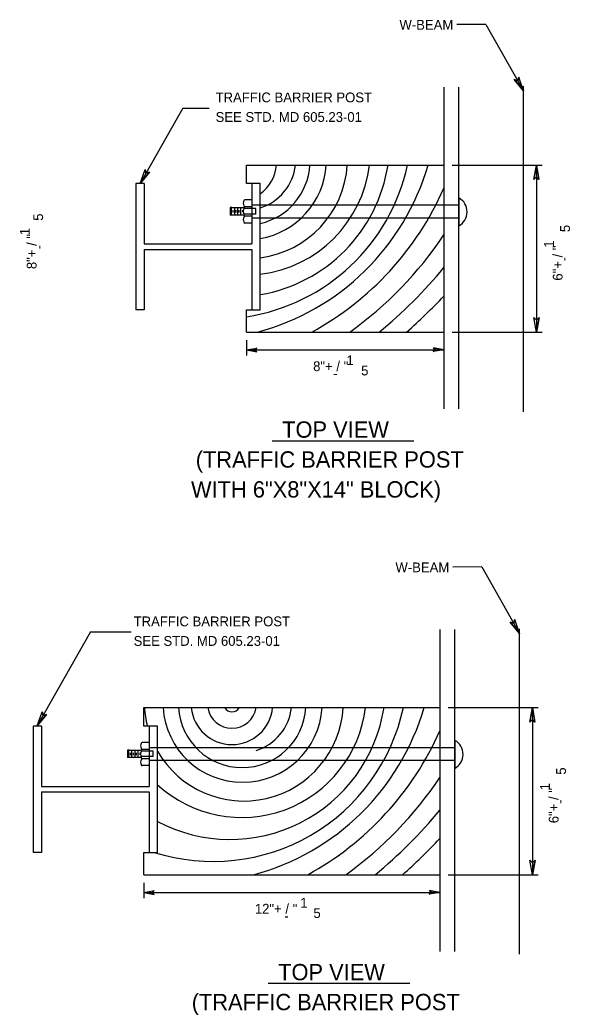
# Model space of a CAD drawing. Extents: x 12.3 to 19.6, y 6 to 16.3.
# Drawn here: x 16.17 to 19.54, y 10.17 to 16.27 of the extents above; entities that cross this region are included whole.
import ezdxf

# ---------------------------------------------------------------- set-up
doc = ezdxf.new("R2010")
doc.units = 0
for name, color, linetype in [('DETL-DIMS', 7, 'Continuous'), ('DETL-LINE', 7, 'Continuous'), ('DETL-NOTE', 7, 'Continuous'), ('DETL-PATT', 7, 'Continuous'), ('DETL-TITL', 7, 'Continuous')]:
    doc.layers.add(name, color=color, linetype=linetype)

msp = doc.modelspace()

# ---------------------------------------------------------------- linework, layer by layer
at = {"layer": 'DETL-DIMS'}
for p, q in [((19.0236, 16.2437), (18.8469, 16.2429)), ((19.0236, 16.2437), (19.2555, 15.8355)), ((19.2197, 15.8986), (19.2251, 15.9211)), ((19.2555, 15.8355), (19.2251, 15.9211)), ((19.2555, 15.8355), (19.1978, 15.9056)), ((19.1978, 15.9056), (19.2197, 15.8986)), ((17.1679, 15.7311), (16.9053, 15.2688)), ((17.1679, 15.7311), (17.3294, 15.7311)), ((18.8167, 15.3816), (19.3689, 15.3816)), ((19.3339, 15.3816), (19.3176, 15.2923)), ((19.3339, 15.3816), (19.3491, 15.2921)), ((19.3339, 15.3816), (19.3339, 14.3573)), ((16.9053, 15.2688), (16.9358, 15.3544)), ((16.9053, 15.2688), (16.963, 15.3389)), ((16.9412, 15.3319), (16.9358, 15.3544)), ((16.963, 15.3389), (16.9412, 15.3319)), ((19.3176, 15.2923), (19.3333, 15.3091)), ((19.3333, 15.3091), (19.3491, 15.2921)), ((19.3339, 14.3573), (19.3187, 14.4469)), ((19.3344, 14.4299), (19.3187, 14.4469)), ((19.3339, 14.3573), (19.3501, 14.4466)), ((19.3501, 14.4466), (19.3344, 14.4299)), ((18.8167, 14.3573), (19.3689, 14.3573)), ((17.5571, 14.3073), (17.5571, 14.2138)), ((17.5571, 14.2488), (17.6218, 14.2598)), ((17.5571, 14.2488), (17.6216, 14.237)), ((17.5571, 14.2488), (18.7667, 14.2488)), ((17.6095, 14.2485), (17.6218, 14.2598)), ((17.6216, 14.237), (17.6095, 14.2485)), ((18.7143, 14.2492), (18.7021, 14.2378)), ((18.7667, 14.2488), (18.7021, 14.2378)), ((18.7667, 14.2488), (18.7022, 14.2606)), ((18.7022, 14.2606), (18.7143, 14.2492)), ((18.999, 12.9184), (18.8223, 12.9176)), ((18.999, 12.9184), (19.2309, 12.5102)), ((19.2309, 12.5102), (19.1732, 12.5803)), ((19.1732, 12.5803), (19.1951, 12.5733)), ((19.1951, 12.5733), (19.2005, 12.5958)), ((19.2309, 12.5102), (19.2005, 12.5958)), ((16.6024, 12.5198), (16.2755, 11.9443)), ((16.6024, 12.5198), (16.8504, 12.5198)), ((16.2755, 11.9443), (16.306, 12.0299)), ((16.3114, 12.0074), (16.306, 12.0299)), ((18.7921, 12.0563), (19.3443, 12.0563)), ((19.3093, 12.0563), (19.293, 11.967)), ((19.3093, 12.0563), (19.3245, 11.9668)), ((19.3093, 12.0563), (19.3093, 11.032)), ((16.2755, 11.9443), (16.3332, 12.0144)), ((16.3332, 12.0144), (16.3114, 12.0074)), ((19.293, 11.967), (19.3087, 11.9838)), ((19.3087, 11.9838), (19.3245, 11.9668)), ((19.3093, 11.032), (19.2941, 11.1216)), ((19.3098, 11.1046), (19.2941, 11.1216)), ((19.3093, 11.032), (19.3255, 11.1213)), ((19.3255, 11.1213), (19.3098, 11.1046)), ((16.9278, 10.982), (16.9278, 10.8885)), ((18.7921, 11.032), (19.3443, 11.032)), ((16.9278, 10.9235), (16.9925, 10.9345)), ((16.9278, 10.9235), (16.9923, 10.9117)), ((16.9278, 10.9235), (18.7421, 10.9235)), ((16.9802, 10.9232), (16.9925, 10.9345)), ((16.9923, 10.9117), (16.9802, 10.9232)), ((18.6897, 10.9239), (18.6775, 10.9125)), ((18.7421, 10.9235), (18.6775, 10.9125)), ((18.7421, 10.9235), (18.6776, 10.9353)), ((18.6776, 10.9353), (18.6897, 10.9239))]:
    msp.add_line(p, q, dxfattribs=at)
for points in [[(19.1978, 15.9056), (19.2555, 15.8355), (19.2251, 15.9211), (19.2197, 15.8986)], [(19.3176, 15.2923), (19.3339, 15.3816), (19.3491, 15.2921), (19.3333, 15.3091)], [(16.963, 15.3389), (16.9053, 15.2688), (16.9358, 15.3544), (16.9412, 15.3319)], [(19.3501, 14.4466), (19.3339, 14.3573), (19.3187, 14.4469), (19.3344, 14.4299)], [(17.6216, 14.237), (17.5571, 14.2488), (17.6218, 14.2598), (17.6095, 14.2485)], [(18.7022, 14.2606), (18.7667, 14.2488), (18.7021, 14.2378), (18.7143, 14.2492)], [(19.1732, 12.5803), (19.2309, 12.5102), (19.2005, 12.5958), (19.1951, 12.5733)], [(16.3332, 12.0144), (16.2755, 11.9443), (16.306, 12.0299), (16.3114, 12.0074)], [(19.293, 11.967), (19.3093, 12.0563), (19.3245, 11.9668), (19.3087, 11.9838)], [(19.3255, 11.1213), (19.3093, 11.032), (19.2941, 11.1216), (19.3098, 11.1046)], [(16.9923, 10.9117), (16.9278, 10.9235), (16.9925, 10.9345), (16.9802, 10.9232)], [(18.6776, 10.9353), (18.7421, 10.9235), (18.6775, 10.9125), (18.6897, 10.9239)]]:
    msp.add_lwpolyline(points, close=True, dxfattribs=at)
at = {"layer": 'DETL-LINE'}
for p, q in [((18.7667, 15.8595), (18.7667, 13.887)), ((18.858, 13.8866), (18.858, 15.8595)), ((19.2555, 13.8699), (19.2555, 15.8652)), ((17.5573, 15.2688), (17.5573, 15.3816)), ((17.5573, 15.3816), (18.7667, 15.3816)), ((16.8799, 15.2688), (16.8799, 14.4944)), ((16.9306, 15.2688), (16.8799, 15.2688)), ((16.9306, 15.2688), (16.9306, 14.8985)), ((17.6418, 15.2688), (17.5573, 15.2688)), ((17.591, 15.2688), (17.591, 14.8985)), ((17.6418, 14.4944), (17.6418, 15.2688)), ((17.591, 15.1679), (17.5471, 15.1679)), ((17.591, 15.1371), (18.8633, 15.1371)), ((18.8584, 15.1808), (18.8577, 15.0083)), ((17.4683, 15.1206), (17.4584, 15.1206)), ((17.4584, 15.1206), (17.4584, 15.0748)), ((17.4832, 15.0749), (17.4584, 15.0749)), ((17.4644, 15.1206), (17.4644, 15.0749)), ((17.4644, 15.1206), (17.4832, 15.1206)), ((17.4832, 15.1206), (17.4832, 15.0749)), ((17.4832, 15.1206), (17.5417, 15.1206)), ((17.541, 15.0749), (17.4832, 15.0749)), ((17.5018, 15.1206), (17.5018, 15.0749)), ((17.5206, 15.1206), (17.5206, 15.0749)), ((17.6147, 15.0812), (17.5392, 15.0812)), ((17.6147, 15.1145), (17.5397, 15.1145)), ((17.591, 15.1258), (17.5471, 15.1258)), ((17.591, 15.0681), (17.5471, 15.0681)), ((17.6147, 15.0812), (17.6147, 15.1145)), ((17.591, 15.026), (17.5471, 15.026)), ((17.591, 15.059), (18.8629, 15.059)), ((16.9306, 14.8985), (17.591, 14.8985)), ((16.9306, 14.8646), (17.591, 14.8646)), ((16.9306, 14.8646), (16.9306, 14.4944)), ((17.591, 14.8646), (17.591, 14.4944)), ((16.9306, 14.4944), (16.8799, 14.4944)), ((17.5571, 14.3573), (17.5571, 14.4944)), ((17.5571, 14.4944), (17.6418, 14.4944)), ((17.5571, 14.3573), (18.7667, 14.3573)), ((18.7421, 12.5342), (18.7421, 10.5617)), ((18.8334, 10.5613), (18.8334, 12.5342)), ((19.2309, 10.5446), (19.2309, 12.5399)), ((16.928, 11.9435), (16.928, 12.0563)), ((16.928, 12.0563), (18.7421, 12.0563)), ((16.2506, 11.9435), (16.2506, 11.1691)), ((16.3013, 11.9435), (16.2506, 11.9435)), ((16.3013, 11.9435), (16.3013, 11.5732)), ((17.0125, 11.9435), (16.928, 11.9435)), ((16.9617, 11.9435), (16.9617, 11.5732)), ((17.0125, 11.1691), (17.0125, 11.9435)), ((16.9617, 11.8426), (16.9178, 11.8426)), ((18.8338, 11.8555), (18.8331, 11.683)), ((16.839, 11.7953), (16.8291, 11.7953)), ((16.8291, 11.7953), (16.8291, 11.7495)), ((16.8351, 11.7953), (16.8351, 11.7496)), ((16.8351, 11.7953), (16.8539, 11.7953)), ((16.8539, 11.7953), (16.8539, 11.7496)), ((16.8539, 11.7953), (16.9124, 11.7953)), ((16.8725, 11.7953), (16.8725, 11.7496)), ((16.8913, 11.7953), (16.8913, 11.7496)), ((16.9854, 11.7892), (16.9104, 11.7892)), ((16.9617, 11.8005), (16.9178, 11.8005)), ((16.9617, 11.8118), (18.8387, 11.8118)), ((16.9854, 11.7559), (16.9854, 11.7892)), ((16.8539, 11.7496), (16.8291, 11.7496)), ((16.9117, 11.7496), (16.8539, 11.7496)), ((16.9854, 11.7559), (16.9099, 11.7559)), ((16.9617, 11.7428), (16.9178, 11.7428)), ((16.9617, 11.7337), (18.8383, 11.7337)), ((16.9617, 11.7007), (16.9178, 11.7007)), ((16.3013, 11.5732), (16.9617, 11.5732)), ((16.3013, 11.5393), (16.9617, 11.5393)), ((16.3013, 11.5393), (16.3013, 11.1691)), ((16.9617, 11.5393), (16.9617, 11.1691)), ((16.3013, 11.1691), (16.2506, 11.1691)), ((16.9278, 11.032), (16.9278, 11.1691)), ((16.9278, 11.1691), (17.0125, 11.1691)), ((16.9278, 11.032), (18.7421, 11.032))]:
    msp.add_line(p, q, dxfattribs=at)
for centre in [(18.8097, 15.0947), (18.7852, 11.7695)]:
    msp.add_arc(centre, 0.0989, 299.0561, 60.46148, dxfattribs=at)
for centre, major_axis, ratio in [((17.5472, 15.1469), (0, -0.021), 0.44218), ((17.5471, 15.097), (0, -0.0288), 0.322403), ((17.5472, 15.0471), (0, -0.021), 0.44218), ((16.9179, 11.8216), (0, -0.021), 0.44218), ((16.9178, 11.7717), (0, -0.0288), 0.322403), ((16.9179, 11.7218), (0, -0.021), 0.44218)]:
    msp.add_ellipse(centre, major_axis=major_axis, ratio=ratio, start_param=3.141593, end_param=6.283185, dxfattribs=at)
at = {"layer": 'DETL-PATT'}
for p, q in [((17.4736, 15.1045), (17.4736, 15.0908)), ((17.4928, 15.1045), (17.4928, 15.0908)), ((17.5103, 15.1041), (17.5103, 15.0902)), ((17.5328, 15.1042), (17.5328, 15.0918)), ((16.8443, 11.7792), (16.8443, 11.7655)), ((16.8635, 11.7792), (16.8635, 11.7655)), ((16.881, 11.7788), (16.881, 11.7649)), ((16.9035, 11.7789), (16.9035, 11.7665))]:
    msp.add_line(p, q, dxfattribs=at)
for centre, radius, start, end in [((17.3775, 15.6307), 1.1921, 278.66609, 347.93652), ((17.2386, 15.7962), 1.4901, 285.06513, 343.84511), ((17.5559, 15.4046), 0.3906, 282.71692, 356.62919), ((17.5584, 15.4123), 0.4883, 279.83898, 356.39995), ((17.5657, 15.4195), 0.6104, 277.16683, 356.43992), ((17.4821, 15.5277), 0.9537, 279.6422, 351.18816), ((17.5526, 15.4708), 0.7629, 276.7148, 353.28774), ((17.5473, 15.4169), 0.3125, 287.61949, 353.51507), ((17.493, 15.405), 0.25, 306.53076, 354.63951), ((17.0624, 15.9911), 1.8626, 298.70219, 336.20554), ((16.8324, 16.249), 2.3283, 305.66021, 326.18168), ((16.5243, 16.6081), 2.9104, 309.34251, 320.39928), ((16.126, 17.0809), 3.638, 311.52688, 316.54201), ((17.5411, 12.0942), 0.6104, 183.55989, 194.29434), ((17.3529, 12.3055), 1.1921, 252.40764, 347.93652), ((17.4575, 12.2024), 0.9537, 242.18754, 351.18816), ((17.528, 12.1455), 0.7629, 227.49418, 353.28774), ((17.5411, 12.0942), 0.6104, 210.00501, 356.44011), ((17.5338, 12.087), 0.4883, 183.59982, 356.40018), ((17.5313, 12.0793), 0.3906, 183.37052, 356.62948), ((17.4684, 12.0797), 0.25, 185.36004, 354.63996), ((17.4684, 12.0797), 0.15, 188.9568, 351.0432), ((17.4684, 12.0797), 0.05, 207.84423, 332.15577), ((17.214, 12.4709), 1.4901, 285.06513, 343.84511), ((17.5227, 12.0916), 0.3125, 287.57318, 353.51507), ((17.0378, 12.6658), 1.8626, 298.70219, 336.20554), ((16.8078, 12.9237), 2.3283, 305.66021, 326.18168), ((16.4997, 13.2828), 2.9104, 309.34251, 320.39928), ((16.1014, 13.7556), 3.638, 311.52688, 316.54201)]:
    msp.add_arc(centre, radius, start, end, dxfattribs=at)
at = {"layer": 'DETL-TITL'}
for p, q in [((17.7146, 13.692), (18.5821, 13.692)), ((17.69, 10.3667), (18.5575, 10.3667))]:
    msp.add_line(p, q, dxfattribs=at)

# ---------------------------------------------------------------- texts
at = {"layer": 'DETL-NOTE'}
for s, p in [('W-BEAM ', (18.4946, 16.2111)), ('TRAFFIC BARRIER POST', (17.3682, 15.7661)), ('SEE STD. MD 605.23-01', (17.3682, 15.6461)), ('1', (18.1701, 14.1552)), ('8"+ / "', (17.9658, 14.1187)), ('5', (18.2598, 14.0923)), ('-', (18.0884, 14.0749)), ('W-BEAM ', (18.47, 12.8858)), ('TRAFFIC BARRIER POST', (16.866, 12.5548)), ('SEE STD. MD 605.23-01', (16.866, 12.4348)), ('1', (17.8866, 10.8299)), ('12"+ / "', (17.6089, 10.7934)), ('5', (17.9674, 10.767)), ('-', (17.7896, 10.7496))]:
    msp.add_text(s, height=0.06, dxfattribs=at).set_placement(p)
for s, p in [('5', (16.3113, 15.0398)), ('5', (19.539, 14.9703)), ('1', (16.2294, 14.9515)), ('8"+ / "', (16.2714, 14.7437)), ('-', (16.3148, 14.8648)), ('1', (19.4408, 14.8747)), ('6"+ / "', (19.4939, 14.673)), ('-', (19.5311, 14.7912)), ('5', (19.5144, 11.645)), ('1', (19.4162, 11.5494)), ('6"+ / "', (19.4693, 11.3477)), ('-', (19.5065, 11.4659))]:
    msp.add_text(s, height=0.06, rotation=90, dxfattribs=at).set_placement(p)
at = {"layer": 'DETL-TITL'}
for s, p in [('TOP VIEW', (17.776, 13.7105)), ('(TRAFFIC BARRIER POST', (17.2465, 13.5271)), ('WITH 6"X8"X14" BLOCK)', (17.2175, 13.3438)), ('TOP VIEW', (17.7515, 10.3852)), ('(TRAFFIC BARRIER POST', (17.2219, 10.2018))]:
    msp.add_text(s, height=0.1, dxfattribs=at).set_placement(p)

doc.saveas('drawing.dxf')
